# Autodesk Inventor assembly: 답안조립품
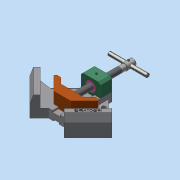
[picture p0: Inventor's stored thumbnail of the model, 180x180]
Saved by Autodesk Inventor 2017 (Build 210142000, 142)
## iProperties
Created: 2020-05
Part Number: 답안조립품
Document SubType Name: Assembly
Designer: 222
Author: 222
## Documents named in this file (11)
- C:\Users\222\Desktop\700506V1042\답안조립품.iam
- C:\Users\222\Desktop\700506V1042\베이스.ipt
- C:\Users\222\Desktop\700506V1042\리드스크류.ipt
- C:\Users\222\Desktop\700506V1042\멈춤나사 M4x5.ipt
- C:\Users\222\Desktop\700506V1042\멈춤나사 M4x10.ipt
- C:\Users\222\Desktop\700506V1042\볼트 M4x16.ipt
- C:\Users\222\Desktop\700506V1042\부시.ipt
- C:\Users\222\Desktop\700506V1042\서포트.ipt
- C:\Users\222\Desktop\700506V1042\조.ipt
- C:\Users\222\Desktop\700506V1042\평행 핀 2.5x24.ipt
- C:\Users\222\Desktop\700506V1042\핸들.ipt
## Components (1 placed, 1 different names)
1. 핸들:1
